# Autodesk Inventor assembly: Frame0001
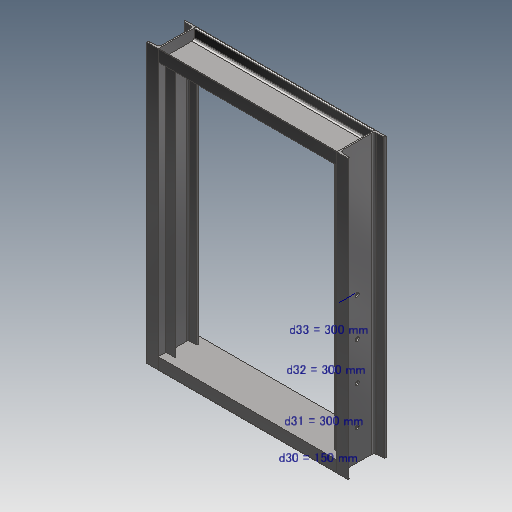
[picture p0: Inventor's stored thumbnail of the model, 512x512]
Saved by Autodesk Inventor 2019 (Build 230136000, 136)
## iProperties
Created: 2018-04
Part Number: Frame0001
Material: 一般
Document SubType Name: Assembly
Designer: shimont
Mass: 398263 g
Surface Area: 90333 cm^2
Volume: 50734.2 cm^3
Density: 7.85 g/cm^3
_FrameDoc: Frame Assembly
_Version: 15.0.0
Author: shimont
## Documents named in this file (14)
- C:\Demo\Inventor_Gate\GateAssy\Frame\Frame0001.iam
- C:\Demo\Inventor_Gate\GateAssy\Frame\Skeleton0001.ipt
- C:\Demo\Inventor_Gate\GateAssy\Frame\JIS 300 x 90 x 10 00000001.ipt
- JIS 300 x 90 x 10 00000001.ipt
- C:\Demo\Inventor_Gate\GateAssy\Frame\JIS 300 x 90 x 10 00000002.ipt
- JIS 300 x 90 x 10 00000002.ipt
- C:\Demo\Inventor_Gate\GateAssy\Frame\JIS 300 x 90 x 10 00000003.ipt
- JIS 300 x 90 x 10 00000003.ipt
- C:\Demo\Inventor_Gate\GateAssy\Frame\JIS 300 x 90 x 10 00000005.ipt
- JIS 300 x 90 x 10 00000005.ipt
- C:\Demo\Inventor_Gate\GateAssy\Frame\JIS 180 x 75 x 7 00000006.ipt
- JIS 180 x 75 x 7 00000006.ipt
- C:\Demo\Inventor_Gate\GateAssy\Frame\JIS 180 x 75 x 7 00000007.ipt
- JIS 180 x 75 x 7 00000007.ipt
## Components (7 placed, 7 different names)
1. フレーム参照モデル
2. JIS 300 x 90 x 10 00000001:1
3. JIS 300 x 90 x 10 00000002:1
4. JIS 300 x 90 x 10 00000003:1
5. JIS 300 x 90 x 10 00000005:1
6. JIS 180 x 75 x 7 00000006:1
7. JIS 180 x 75 x 7 00000007:1
